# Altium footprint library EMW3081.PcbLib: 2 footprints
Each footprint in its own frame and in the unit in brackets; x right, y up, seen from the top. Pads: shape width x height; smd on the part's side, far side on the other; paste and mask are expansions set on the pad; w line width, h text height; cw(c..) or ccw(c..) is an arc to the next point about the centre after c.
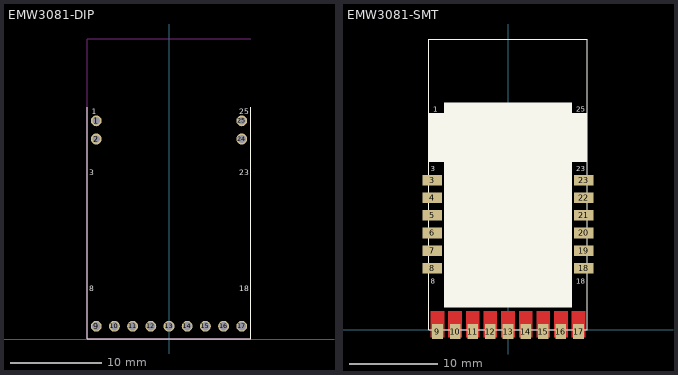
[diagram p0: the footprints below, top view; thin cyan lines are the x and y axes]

## EMW3081-DIP [mm]
pads (13):
  round 1.2 hole 0.8: 1(-8,24.001) 2(-8,22.001) 25(8,24.001)
  round 1.2 hole 0.9: 9(-8,1.401) 10(-6,1.401) 11(-4,1.401) 12(-2,1.401) 13(0,1.401) 14(2,1.401) 15(4,1.401) 16(6,1.401) 17(8,1.401) 24(8,22.001)
Top Overlay:
  lines w0.1: -9,25.501 -9,0.001 9,0.001 9,25.501
  text "25" at 7.75,24.751 h0.6
  text "23" at 7.75,18.001 h0.6
  text "18" at 7.75,5.251 h0.6
  text "8" at -8.75,5.251 h0.6
  text "3" at -8.75,18.001 h0.6
  text "1" at -8.5,24.751 h0.6
Keep-Out Layer:
  lines w0.1: 9,33.001 -9,33.001 -9,0.001 ; -9,0.001 9,0.001 -9,0.001
3D body: height 1.2, standoff 0.01, extent -8.501,0 -7.5,0.491
3D body: height 1.2, standoff 0.01, extent -6.5,0 -5.5,0.491
3D body: height 1.2, standoff 0.01, extent -4.501,0 -3.5,0.491
3D body: height 1.2, standoff 0.01, extent -2.501,0 -1.5,0.491
3D body: height 1.2, standoff 0.01, extent -0.5,0 0.5,0.491
3D body: height 1.2, standoff 0.01, extent 3.5,0 4.5,0.491
3D body: height 1.2, standoff 0.01, extent 1.499,0 2.5,0.491
3D body: height 1.2, standoff 0.01, extent 7.5,0 8.5,0.491
3D body: height 1.2, standoff 0.01, extent 5.499,0 6.5,0.491
3D body: height 1.2, standoff 0.01, extent 8.51,6.501 9.001,7.501
3D body: height 1.2, standoff 0.01, extent 8.51,8.501 9.001,9.502
3D body: height 1.2, standoff 0.01, extent 8.51,12.501 9.001,13.502
3D body: height 1.2, standoff 0.01, extent 8.51,10.501 9.001,11.501
3D body: height 1.2, standoff 0.01, extent 8.51,16.501 9.001,17.502
3D body: height 1.2, standoff 0.01, extent 8.51,14.501 9.001,15.501
3D body: height 1.2, standoff 0.01, extent -9.001,8.501 -8.51,9.501
3D body: height 1.2, standoff 0.01, extent -9.001,6.501 -8.51,7.501
3D body: height 1.2, standoff 0.01, extent -9.001,12.501 -8.51,13.501
3D body: height 1.2, standoff 0.01, extent -9.001,10.5 -8.51,11.501
3D body: height 1.2, standoff 0.01, extent -9.001,14.5 -8.51,15.501
3D body: height 1.2, standoff 0.01, extent -9.001,16.501 -8.51,17.501
3D body: height 1.2, standoff 0.01, extent -7.489,25.604 7.523,32.691
3D body: height 2, standoff 1.2, extent -7.209,2.566 7.218,24.131
3D body: height 1.2, standoff 0, extent 7.401,0.801 8.6,2.001
3D body: height 1.2, standoff 0, extent 5.401,0.801 6.6,2.001
3D body: height 1.2, standoff 0, extent 3.401,0.801 4.6,2.001
3D body: height 1.2, standoff 0, extent 1.401,0.801 2.6,2.001
3D body: height 1.2, standoff 0, extent -0.599,0.801 0.6,2.001
3D body: height 1.2, standoff 0, extent -2.599,0.801 -1.4,2.001
3D body: height 1.2, standoff 0, extent -4.599,0.801 -3.4,2.001
3D body: height 1.2, standoff 0, extent -6.599,0.801 -5.4,2.001
3D body: height 1.2, standoff 0, extent -8.599,0.801 -7.4,2.001
3D body: height 1.2, standoff 0, extent 7.701,1.101 8.3,1.701
3D body: height 1.2, standoff 0, extent 5.701,1.101 6.3,1.701
3D body: height 1.2, standoff 0, extent 3.701,1.101 4.3,1.701
3D body: height 1.2, standoff 0, extent 1.701,1.101 2.3,1.701
3D body: height 1.2, standoff 0, extent -0.299,1.101 0.3,1.701
3D body: height 1.2, standoff 0, extent -2.299,1.101 -1.7,1.701
3D body: height 1.2, standoff 0, extent -4.299,1.101 -3.7,1.701
3D body: height 1.2, standoff 0, extent -6.299,1.101 -5.7,1.701
3D body: height 1.2, standoff 0, extent -8.299,1.101 -7.7,1.701
3D body: height 1.2, standoff 0, extent 7.701,23.701 8.3,24.301
3D body: height 1.2, standoff 0, extent 7.701,21.701 8.3,22.301
3D body: height 1.2, standoff 0, extent -8.299,21.701 -7.7,22.301
3D body: height 1.2, standoff 0, extent -8.299,23.701 -7.7,24.301
3D body: height 1.2, standoff 0, extent 7.401,21.401 8.6,22.601
3D body: height 1.2, standoff 0, extent 7.401,23.401 8.6,24.601
3D body: height 1.2, standoff 0, extent -8.599,21.401 -7.4,22.601
3D body: height 1.2, standoff 0, extent -8.599,23.401 -7.4,24.601
3D body: height 1.2, standoff 0, extent -9,0.001 9,33.001
3D body "SW3dPS-U.FL-R-SMT-1.STEP": height 2.45, standoff 1.19, extent 3.807,22.198 6.907,25.198

## EMW3081-SMT [mm]
pads (21):
  rect 2.2x1.2 smd: 3(-8.6,17) 4(-8.6,15) 5(-8.6,13) 6(-8.6,11) 7(-8.6,9) 8(-8.6,7) 18(8.6,7) 19(8.6,9) 20(8.6,11) 21(8.6,13) 22(8.6,15) 23(8.6,17)
  rect 1.2x1.7 smd: 9(-8,-0.175) 10(-6,-0.175) 11(-4,-0.175) 12(-2,-0.175) 13(0,-0.175) 14(2,-0.175) 15(4,-0.175) 16(6,-0.175) 17(8,-0.175)
Top Layer:
  pour cut-out: -8.75,-0.85 -8.75,2.15 -7.25,2.15 -7.25,-0.85
  pour cut-out: -6.75,-0.85 -6.75,2.15 -5.25,2.15 -5.25,-0.85
  pour cut-out: -4.75,-0.85 -4.75,2.15 -3.25,2.15 -3.25,-0.85
  pour cut-out: -2.75,-0.85 -2.75,2.15 -1.25,2.15 -1.25,-0.85
  pour cut-out: -0.75,-0.85 -0.75,2.15 0.75,2.15 0.75,-0.85
  pour cut-out: 1.25,-0.85 1.25,2.15 2.75,2.15 2.75,-0.85
  pour cut-out: 3.25,-0.85 3.25,2.15 4.75,2.15 4.75,-0.85
  pour cut-out: 5.25,-0.85 5.25,2.15 6.75,2.15 6.75,-0.85
  pour cut-out: 7.25,-0.85 7.25,2.15 8.75,2.15 8.75,-0.85
Top Overlay:
  rectangle: 7.214,19.05 9,24.613
  rectangle: -9,19.075 -7.214,24.613
  region: -7.209,2.565 7.218,2.565 7.214,25.756 -7.209,25.756 -7.209,19.888
  lines w0.1: -9,0 -9,33 9,33 9,0 ; -9,0.001 9,0.001
  text "1" at -8.5,24.75 h0.6
  text "3" at -8.75,18 h0.6
  text "8" at -8.75,5.25 h0.6
  text "18" at 7.75,5.25 h0.6
  text "23" at 7.75,18 h0.6
  text "25" at 7.75,24.75 h0.6
Keep-Out Layer:
  lines w0.1: -9,0 -9,33 9,33
Mechanical 15:
  lines w0.1: -0.354,14.396 0.354,15.104 ; -0.354,15.104 0.354,14.396
3D body: height 1.2, standoff 0.01, extent -8.501,0 -7.5,0.491
3D body: height 1.2, standoff 0.01, extent -6.5,0 -5.5,0.491
3D body: height 1.2, standoff 0.01, extent -4.501,0 -3.5,0.491
3D body: height 1.2, standoff 0.01, extent -2.501,0 -1.5,0.491
3D body: height 1.2, standoff 0.01, extent -0.5,0 0.5,0.491
3D body: height 1.2, standoff 0.01, extent 3.5,0 4.5,0.491
3D body: height 1.2, standoff 0.01, extent 1.499,0 2.5,0.491
3D body: height 1.2, standoff 0.01, extent 7.5,0 8.5,0.491
3D body: height 1.2, standoff 0.01, extent 5.499,0 6.5,0.491
3D body: height 1.2, standoff 0, extent 7.4,0.804 8.599,2.004
3D body: height 1.2, standoff 0, extent 5.4,0.804 6.599,2.004
3D body: height 1.2, standoff 0, extent 3.4,0.804 4.599,2.004
3D body: height 1.2, standoff 0, extent 1.4,0.804 2.599,2.004
3D body: height 1.2, standoff 0, extent -0.6,0.804 0.599,2.004
3D body: height 1.2, standoff 0, extent -2.6,0.804 -1.401,2.004
3D body: height 1.2, standoff 0, extent -4.6,0.804 -3.401,2.004
3D body: height 1.2, standoff 0, extent -6.6,0.804 -5.401,2.004
3D body: height 1.2, standoff 0, extent -8.6,0.804 -7.401,2.004
3D body: height 1.2, standoff 0, extent 7.7,1.104 8.299,1.704
3D body: height 1.2, standoff 0, extent 5.7,1.104 6.299,1.704
3D body: height 1.2, standoff 0, extent 3.7,1.104 4.299,1.704
3D body: height 1.2, standoff 0, extent 1.7,1.104 2.299,1.704
3D body: height 1.2, standoff 0, extent -0.3,1.104 0.299,1.704
3D body: height 1.2, standoff 0, extent -2.3,1.104 -1.701,1.704
3D body: height 1.2, standoff 0, extent -4.3,1.104 -3.701,1.704
3D body: height 1.2, standoff 0, extent -6.3,1.104 -5.701,1.704
3D body: height 1.2, standoff 0, extent -8.3,1.104 -7.701,1.704
3D body "SW3dPS-U.FL-R-SMT-1.STEP": height 2.45, standoff 1.19, extent 3.807,22.197 6.907,25.197
3D body: height 1.2, standoff 0, extent -9,0 9,33
3D body: height 1.2, standoff 0, extent -8.599,23.4 -7.4,24.6
3D body: height 1.2, standoff 0, extent -8.599,21.4 -7.4,22.6
3D body: height 1.2, standoff 0, extent 7.401,23.4 8.6,24.6
3D body: height 1.2, standoff 0, extent 7.401,21.4 8.6,22.6
3D body: height 1.2, standoff 0, extent -8.299,23.7 -7.7,24.3
3D body: height 1.2, standoff 0, extent -8.299,21.7 -7.7,22.3
3D body: height 1.2, standoff 0, extent 7.701,21.7 8.3,22.3
3D body: height 1.2, standoff 0, extent 7.701,23.7 8.3,24.3
3D body: height 2, standoff 1.2, extent -7.209,2.565 7.218,24.13
3D body: height 1.2, standoff 0.01, extent -7.489,25.603 7.523,32.69
3D body: height 1.2, standoff 0.01, extent -9.001,16.5 -8.51,17.5
3D body: height 1.2, standoff 0.01, extent -9.001,14.499 -8.51,15.5
3D body: height 1.2, standoff 0.01, extent -9.001,10.499 -8.51,11.5
3D body: height 1.2, standoff 0.01, extent -9.001,12.5 -8.51,13.5
3D body: height 1.2, standoff 0.01, extent -9.001,6.499 -8.51,7.5
3D body: height 1.2, standoff 0.01, extent -9.001,8.5 -8.51,9.5
3D body: height 1.2, standoff 0.01, extent 8.51,14.5 9.001,15.5
3D body: height 1.2, standoff 0.01, extent 8.51,16.5 9.001,17.501
3D body: height 1.2, standoff 0.01, extent 8.51,10.5 9.001,11.5
3D body: height 1.2, standoff 0.01, extent 8.51,12.5 9.001,13.501
3D body: height 1.2, standoff 0.01, extent 8.51,8.5 9.001,9.501
3D body: height 1.2, standoff 0.01, extent 8.51,6.5 9.001,7.5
